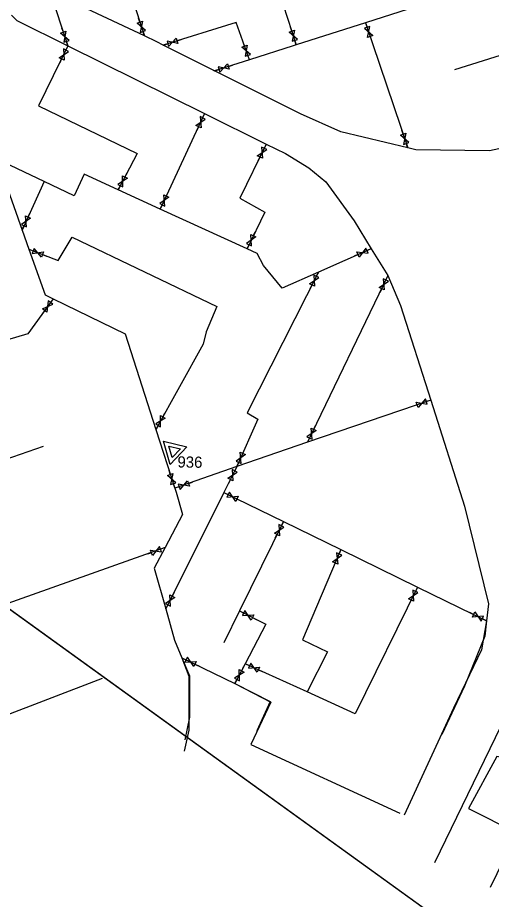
# Model space of a CAD drawing. Extents: x 349903 to 372392, y 368574 to 383062.
# Drawn here: x 362258.2 to 362470.3, y 371926.1 to 372320.7 of the extents above; entities that cross this region are included whole.
import ezdxf

# ---------------------------------------------------------------- set-up
doc = ezdxf.new("R2010")
doc.units = 0
for name, color, linetype in [('Niveau 1', 7, 'Continuous'), ('Niveau 10', 7, 'Continuous'), ('Niveau 2', 7, 'Continuous'), ('Niveau 20', 7, 'Continuous')]:
    doc.layers.add(name, color=color, linetype=linetype)

msp = doc.modelspace()

# ---------------------------------------------------------------- linework, layer by layer
at = {"layer": 'Niveau 1'}
for p, q in [((362312.901, 372318.619), (362312.311, 372320.426)), ((362278.645, 372314.165), (362278.041, 372315.968)), ((362380.953, 372314.622), (362380.373, 372316.433)), ((362413.947, 372318.356), (362414.616, 372316.361)), ((362314.913, 372312.455), (362314.26, 372314.456)), ((362416.009, 372312.209), (362416.614, 372310.406)), ((362280.706, 372308.017), (362279.785, 372306.125)), ((362280.706, 372308.017), (362280.038, 372310.012)), ((362323.4, 372308.363), (362325.413, 372308.977)), ((362329.602, 372310.255), (362331.42, 372310.81)), ((362359.81, 372307.915), (362359.169, 372309.705)), ((362382.928, 372308.446), (362382.287, 372310.45)), ((362277.869, 372302.186), (362277.037, 372300.477)), ((362361.996, 372301.811), (362361.287, 372303.792)), ((362346.346, 372296.854), (362348.352, 372297.49)), ((362352.526, 372298.816), (362354.338, 372299.392)), ((362341.902, 372277.745), (362341.015, 372275.837)), ((362339.17, 372271.865), (362338.369, 372270.14)), ((362430.779, 372268.498), (362430.181, 372270.303)), ((362369.488, 372264.1), (362368.553, 372262.215)), ((362432.816, 372262.342), (362432.155, 372264.34)), ((362366.608, 372258.291), (362365.764, 372256.587)), ((362306.239, 372249.344), (362307.115, 372251.032)), ((362303.253, 372243.589), (362304.222, 372245.457)), ((362324.788, 372240.863), (362325.601, 372242.582)), ((362322.017, 372235.001), (362322.917, 372236.903)), ((362262.833, 372231.49), (362263.617, 372233.222)), ((362260.16, 372225.583), (362261.028, 372227.5)), ((362363.695, 372223.054), (362364.508, 372224.773)), ((362360.922, 372217.193), (362361.822, 372219.095)), ((362416.503, 372217.243), (362414.574, 372216.402)), ((362263.222, 372217.005), (362265.182, 372216.239)), ((362269.261, 372214.646), (362271.032, 372213.954)), ((362410.56, 372214.651), (362408.817, 372213.891)), ((362392.834, 372206.79), (362391.886, 372204.911)), ((362423.938, 372205.202), (362423.041, 372203.299)), ((362389.913, 372201.001), (362389.056, 372199.304)), ((362421.174, 372199.336), (362420.364, 372197.616)), ((362274.091, 372194.892), (362272.856, 372193.188)), ((362270.285, 372189.642), (362269.169, 372188.103)), ((362437.033, 372147.457), (362435.234, 372146.843)), ((362443.17, 372149.55), (362441.178, 372148.871)), ((362323.201, 372142.052), (362324.12, 372143.716)), ((362321.088, 372138.226), (362320.066, 372136.376)), ((362390.772, 372136.479), (362391.599, 372138.191)), ((362387.953, 372130.64), (362388.868, 372132.535)), ((362358.986, 372125.698), (362359.769, 372127.431)), ((362356.317, 372119.789), (362355.382, 372117.903)), ((362356.317, 372119.789), (362357.184, 372121.707)), ((362326.532, 372116.242), (362325.95, 372118.052)), ((362327.868, 372112.081), (362328.514, 372110.069)), ((362330.509, 372110.766), (362328.514, 372110.069)), ((362330.509, 372110.766), (362328.514, 372110.069)), ((362334.635, 372112.209), (362336.429, 372112.836)), ((362334.635, 372112.209), (362336.429, 372112.836)), ((362353.437, 372113.98), (362352.593, 372112.276)), ((362350.525, 372108.182), (362352.417, 372107.261)), ((362356.356, 372105.345), (362358.065, 372104.514)), ((362377.156, 372095.184), (362376.206, 372093.306)), ((362374.231, 372089.397), (362373.374, 372087.7)), ((362324.166, 372083.535), (362322.198, 372082.79)), ((362318.102, 372081.239), (362316.324, 372080.565)), ((362402.932, 372082.602), (362402.097, 372080.67)), ((362400.361, 372076.649), (362399.607, 372074.904)), ((362327.479, 372061.822), (362328.357, 372063.508)), ((362437.223, 372065.864), (362436.288, 372063.979)), ((362434.343, 372060.055), (362433.499, 372058.351)), ((362324.486, 372056.07), (362325.458, 372057.937)), ((362357.506, 372055.178), (362359.382, 372054.224)), ((362363.286, 372052.241), (362364.982, 372051.379)), ((362462.343, 372053.609), (362460.635, 372054.444)), ((362468.168, 372050.76), (362466.278, 372051.685)), ((362331.717, 372034.238), (362333.614, 372033.327)), ((362337.562, 372031.432), (362339.277, 372030.609)), ((362358.484, 372028.426), (362359.362, 372030.112)), ((362360.077, 372031.565), (362361.995, 372030.698)), ((362365.986, 372028.895), (362367.718, 372028.112)), ((362355.487, 372022.676), (362356.46, 372024.542))]:
    msp.add_line(p, q, dxfattribs=at)
for points in [[(362311.697, 372318.222), (362314.093, 372319.012), (362313.05, 372314.075), (362315.452, 372314.851)], [(362417.21, 372312.616), (362414.821, 372311.806), (362415.823, 372316.751), (362413.428, 372315.956)], [(362277.444, 372313.758), (362279.834, 372314.567), (362278.83, 372309.622), (362281.226, 372310.417)], [(362379.746, 372314.231), (362382.147, 372315.008), (362381.075, 372310.077), (362383.481, 372310.838)], [(362329.228, 372311.467), (362329.972, 372309.056), (362325.056, 372310.194), (362325.785, 372307.778)], [(362358.617, 372307.484), (362360.99, 372308.342), (362360.088, 372303.378), (362362.466, 372304.221)], [(362279.011, 372301.635), (362276.739, 372302.732), (362280.92, 372305.557), (362278.653, 372306.669)], [(362352.138, 372300.024), (362352.909, 372297.621), (362347.981, 372298.704), (362348.737, 372296.296)], [(362340.322, 372271.334), (362338.03, 372272.39), (362342.16, 372275.29), (362339.874, 372276.36)], [(362429.576, 372268.095), (362431.969, 372268.896), (362430.947, 372263.955), (362433.345, 372264.74)], [(362367.746, 372257.731), (362365.482, 372258.845), (362369.683, 372261.639), (362367.426, 372262.767)], [(362305.112, 372249.925), (362307.355, 372248.77), (362303.103, 372246.053), (362305.339, 372244.884)], [(362323.64, 372241.401), (362325.925, 372240.33), (362321.776, 372237.458), (362324.054, 372236.372)], [(362261.676, 372232.009), (362263.978, 372230.976), (362259.878, 372228.036), (362262.174, 372226.988)], [(362362.547, 372223.593), (362364.831, 372222.521), (362360.682, 372219.65), (362362.959, 372218.564)], [(362269.719, 372215.828), (362268.808, 372213.475), (362265.656, 372217.415), (362264.731, 372215.068)], [(362411.07, 372213.49), (362410.054, 372215.8), (362415.068, 372215.234), (362414.067, 372217.55)], [(362391.047, 372200.434), (362388.79, 372201.563), (362393.012, 372204.328), (362390.763, 372205.472)], [(362422.323, 372198.8), (362420.037, 372199.868), (362424.182, 372202.745), (362421.903, 372203.828)], [(362271.314, 372188.901), (362269.267, 372190.376), (362273.874, 372192.433), (362271.836, 372193.92)], [(362437.447, 372146.258), (362436.624, 372148.643), (362441.575, 372147.666), (362440.767, 372150.057)], [(362322.089, 372142.661), (362324.302, 372141.448), (362319.98, 372138.843), (362322.185, 372137.616)], [(362389.629, 372137.027), (362391.904, 372135.937), (362387.732, 372133.099), (362390.001, 372131.994)], [(362357.829, 372126.216), (362360.132, 372125.185), (362356.033, 372122.241), (362358.33, 372121.195)], [(362325.325, 372115.851), (362327.725, 372116.63), (362326.659, 372111.698), (362329.064, 372112.462)], [(362354.575, 372113.421), (362352.31, 372114.534), (362356.513, 372117.328), (362354.255, 372118.456)], [(362334.212, 372113.404), (362335.053, 372111.025), (362330.095, 372111.965), (362330.92, 372109.581)], [(362334.212, 372113.404), (362335.053, 372111.025), (362330.095, 372111.965), (362330.92, 372109.581)], [(362356.907, 372106.487), (362355.81, 372104.215), (362352.985, 372108.396), (362351.873, 372106.13)], [(362375.365, 372088.829), (362373.109, 372089.96), (362377.332, 372092.722), (362375.084, 372093.867)], [(362318.555, 372080.055), (362317.654, 372082.411), (362322.634, 372081.599), (362321.748, 372083.962)], [(362401.527, 372076.15), (362399.207, 372077.144), (362403.256, 372080.155), (362400.943, 372081.163)], [(362435.481, 372059.495), (362433.217, 372060.609), (362437.418, 372063.403), (362435.161, 372064.531)], [(362326.353, 372062.403), (362328.595, 372061.246), (362324.339, 372058.534), (362326.574, 372057.362)], [(362363.857, 372053.373), (362362.721, 372051.12), (362359.969, 372055.349), (362358.819, 372053.103)], [(362461.79, 372052.468), (362462.891, 372054.738), (362465.708, 372050.552), (362466.824, 372052.815)], [(362338.107, 372032.577), (362337.023, 372030.299), (362334.175, 372034.465), (362333.076, 372032.193)], [(362366.504, 372030.052), (362365.472, 372027.75), (362362.529, 372031.848), (362361.483, 372029.552)], [(362357.357, 372029.008), (362359.598, 372027.849), (362355.341, 372025.14), (362357.576, 372023.967)]]:
    msp.add_lwpolyline(points, close=True, dxfattribs=at)
at = {"layer": 'Niveau 10'}
for p, q in [((362304.645, 372344.422), (362314.913, 372312.455)), ((362413.947, 372318.356), (362432.816, 372262.342)), ((362490.677, 372308.847), (362453.772, 372297.302)), ((362341.902, 372277.745), (362322.017, 372235.001)), ((362270.042, 372247.295), (362260.16, 372225.583)), ((362423.938, 372205.202), (362387.953, 372130.64)), ((362443.17, 372149.55), (362387.953, 372130.64)), ((362387.953, 372130.64), (362356.317, 372119.789)), ((362206.565, 372107.249), (362269.694, 372128.837)), ((362356.317, 372119.789), (362328.514, 372110.069)), ((362356.326, 372119.792), (362350.525, 372108.182)), ((362350.525, 372108.182), (362324.486, 372056.07)), ((362350.525, 372108.182), (362377.156, 372095.184)), ((362377.156, 372095.184), (362357.506, 372055.178)), ((362377.156, 372095.184), (362402.932, 372082.602)), ((362324.166, 372083.535), (362227.548, 372049.261)), ((362402.932, 372082.602), (362437.223, 372065.864)), ((362437.223, 372065.864), (362468.168, 372050.76)), ((362357.506, 372055.178), (362350.478, 372040.869)), ((362243.732, 372004.951), (362296.22, 372025.084)), ((362485.697, 372026.903), (362444.861, 371942.512))]:
    msp.add_line(p, q, dxfattribs=at)
for points in [[(362520.21, 372351.85), (362444.202, 372328.022), (362413.947, 372318.356)], [(362371.209, 372344.417), (362382.928, 372308.446)], [(362314.913, 372312.455), (362272.581, 372332.449)], [(362272.581, 372332.449), (362280.706, 372308.017)], [(362255.361, 372321.695), (362257.869, 372319.313), (362280.706, 372308.017)], [(362361.996, 372301.811), (362356.082, 372318.422), (362323.4, 372308.363)], [(362413.947, 372318.356), (362382.928, 372308.446)], [(362323.4, 372308.363), (362320.551, 372309.792), (362314.913, 372312.455)], [(362280.706, 372308.017), (362267.579, 372281.214), (362311.65, 372259.838), (362303.253, 372243.589)], [(362280.706, 372308.017), (362341.902, 372277.745)], [(362345.761, 372297.147), (362346.346, 372296.854), (362323.4, 372308.363)], [(362382.928, 372308.446), (362381.601, 372308.022), (362361.996, 372301.811)], [(362361.996, 372301.811), (362346.346, 372296.854)], [(362432.816, 372262.342), (362402.842, 372269.523), (362384.778, 372277.577), (362346.346, 372296.854)], [(362341.902, 372277.745), (362369.488, 372264.1)], [(362369.488, 372264.1), (362357.657, 372239.919), (362368.795, 372233.603), (362360.922, 372217.193)], [(362369.488, 372264.1), (362378.163, 372259.809), (362388.582, 372253.479), (362396.159, 372247.149), (362408.789, 372229.741), (362416.503, 372217.243)], [(362482.515, 372263.933), (362469.494, 372261.129), (362436.46, 372261.469), (362432.816, 372262.342)], [(362248.825, 372257.346), (362260.16, 372225.583)], [(362270.042, 372247.295), (362248.825, 372257.346)], [(362303.253, 372243.589), (362287.92, 372250.607), (362283.561, 372240.891), (362270.042, 372247.295)], [(362322.017, 372235.001), (362303.253, 372243.589)], [(362360.922, 372217.193), (362322.017, 372235.001)], [(362260.16, 372225.583), (362263.222, 372217.005)], [(362263.222, 372217.005), (362276.296, 372211.933), (362282.575, 372222.423), (362347.374, 372191.397), (362342.653, 372180.063), (362341.174, 372174.589), (362320.066, 372136.376)], [(362392.834, 372206.79), (362376.544, 372199.596), (362368.311, 372209.798), (362365.405, 372215.142), (362360.922, 372217.193)], [(362416.503, 372217.243), (362392.834, 372206.79)], [(362416.503, 372217.243), (362423.938, 372205.202)], [(362263.222, 372217.005), (362270.485, 372196.651), (362274.091, 372194.892)], [(362392.834, 372206.79), (362360.902, 372143.834), (362365.733, 372140.972), (362356.317, 372119.789)], [(362423.938, 372205.202), (362429.627, 372191.887), (362443.17, 372149.55)], [(362274.091, 372194.892), (362262.702, 372179.101), (362187.617, 372156.898)], [(362274.091, 372194.892), (362306.322, 372179.174), (362320.066, 372136.376)], [(362443.17, 372149.55), (362458.265, 372102.09), (362469, 372058.381), (362468.168, 372050.76)], [(362320.066, 372136.376), (362328.514, 372110.069)], [(362328.514, 372110.069), (362329.084, 372108.293), (362331.99, 372098.303)], [(362331.99, 372098.303), (362324.166, 372083.535)], [(362324.166, 372083.535), (362319.317, 372074.38), (362324.486, 372056.07)], [(362402.932, 372082.602), (362385.644, 372042.228), (362396.975, 372036.94), (362387.808, 372018.951)], [(362437.223, 372065.864), (362409.232, 372009.206), (362387.808, 372018.951)], [(362324.486, 372056.07), (362328.432, 372042.09), (362331.717, 372034.238)], [(362357.506, 372055.178), (362369.233, 372049.296), (362360.077, 372031.565)], [(362468.168, 372050.76), (362465.83, 372037.709), (362453.262, 372011.658), (362431.194, 371963.869)], [(362468.168, 372050.76), (362467.422, 372043.935), (362458.265, 372021.447), (362448.059, 371999.847)], [(362331.717, 372034.238), (362334.762, 372026.031), (362334.762, 372001.776), (362332.772, 371992.389)], [(362331.717, 372034.238), (362335.11, 372026.125), (362335.11, 372007.586), (362332.965, 371997.55)], [(362331.717, 372034.238), (362355.487, 372022.676)], [(362360.077, 372031.565), (362355.487, 372022.676)], [(362387.808, 372018.951), (362360.077, 372031.565)], [(362355.487, 372022.676), (362371.569, 372014.352), (362362.591, 371995.488), (362429.281, 371964.745)], [(362355.487, 372022.676), (362371.186, 372014.664), (362365.284, 372001.472)], [(362493.31, 372023.388), (362477.138, 371989.2), (362472.649, 371990.098), (362460.081, 371966.742), (362481.626, 371955.962), (362469.77, 371931.456)]]:
    msp.add_lwpolyline(points, dxfattribs=at)
at = {"layer": 'Niveau 2'}
for points in [[(362333.942, 372128.555), (362326.514, 372120.772), (362323.488, 372131.096)], [(362331.09, 372127.683), (362327.376, 372123.793), (362325.865, 372128.956)]]:
    msp.add_lwpolyline(points, close=True, dxfattribs=at)
at = {"layer": 'Niveau 20'}
for points in [[(365165.277, 375764.604), (367014.204, 373077.161), (365116.287, 370509.391), (363702.153, 371011.781), (361432.095, 372649.199), (361533.395, 373713.771)], [(361432.095, 372649.199), (359273.68, 370583.819), (361376.274, 368741.723), (363534.689, 368816.151), (365116.287, 370509.391), (363702.153, 371011.781)]]:
    msp.add_lwpolyline(points, close=True, dxfattribs=at)

# ---------------------------------------------------------------- texts
at = {"layer": 'Niveau 2'}
msp.add_text('936', height=5, rotation=359, dxfattribs=at).set_placement((362329.7, 372119.392))

doc.saveas('drawing.dxf')
